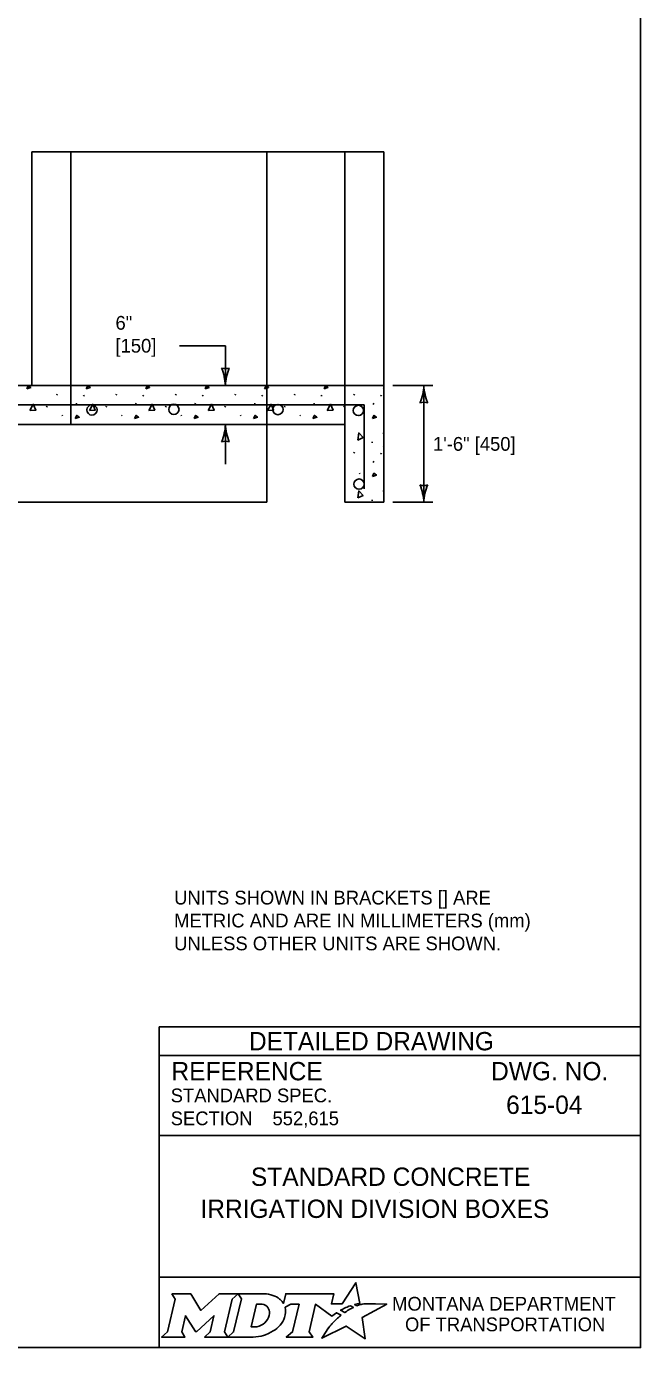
# Model space of a CAD drawing. Extents: x 49991.4 to 50021, y 49987.6 to 50011.4.
# Drawn here: x 50014.07 to 50016.75, y 49987.8 to 49993.57 of the extents above; entities that cross this region are included whole.
import ezdxf

# ---------------------------------------------------------------- set-up
doc = ezdxf.new("R2010")
doc.units = 0
for name, color, linetype in [('Default', 7, 'Continuous'), ('Level 1', 7, 'Continuous'), ('Level 2', 7, 'Continuous'), ('Level 3', 7, 'Continuous'), ('Level 4', 7, 'Continuous'), ('Level 5', 7, 'Continuous')]:
    doc.layers.add(name, color=color, linetype=linetype)

msp = doc.modelspace()

# ---------------------------------------------------------------- linework, layer by layer
at = {"layer": 'Default'}
for points in [[(50015.5126, 49987.9811), (50015.5023, 49987.9867), (50015.5139, 49987.9895), (50015.5255, 49987.9915), (50015.5081, 49988.0816), (50015.4486, 49987.9903), (50015.4013, 49987.9896), (50015.4116, 49988.0337), (50015.2024, 49988.0338), (50015.1923, 49987.9913), (50015.1865, 49987.9996)], [(50014.7056, 49988.0338), (50014.7197, 49988.0104), (50014.6862, 49987.8671), (50014.6605, 49987.8446), (50014.7621, 49987.8446), (50014.7486, 49987.8674), (50014.7648, 49987.9375), (50014.8085, 49987.8685), (50014.8138, 49987.8685), (50014.8889, 49987.938), (50014.8725, 49987.8669), (50014.8478, 49987.8449), (50014.9494, 49987.8449), (50014.9356, 49987.8682), (50014.9688, 49988.0106)], [(50014.9688, 49988.0106), (50014.9941, 49988.0338), (50014.9117, 49988.0338), (50014.8321, 49987.9608), (50014.7876, 49988.0335), (50014.7056, 49988.0338)], [(50015.1077, 49988.0338), (50014.9941, 49988.0338), (50015.0088, 49988.0109), (50014.9749, 49987.8671), (50014.9494, 49987.8449), (50015.06, 49987.8449)], [(50015.1317, 49987.9471), (50015.1305, 49987.939), (50015.1273, 49987.9297), (50015.1231, 49987.9215), (50015.1175, 49987.914), (50015.111, 49987.9071), (50015.1031, 49987.9008), (50015.0948, 49987.8961), (50015.0857, 49987.8922), (50015.0766, 49987.8899), (50015.0674, 49987.889), (50015.0515, 49987.889), (50015.0751, 49987.989), (50015.0911, 49987.989), (50015.0987, 49987.9884), (50015.1063, 49987.9865), (50015.1129, 49987.9835), (50015.119, 49987.9793), (50015.1238, 49987.9743), (50015.1275, 49987.9683), (50015.1302, 49987.9621), (50015.1318, 49987.9547), (50015.1318, 49987.9517), (50015.1317, 49987.9471)], [(50015.1991, 49987.9747), (50015.2237, 49987.9878), (50015.2606, 49987.9878), (50015.232, 49987.8673), (50015.2045, 49987.8446), (50015.3207, 49987.8446), (50015.3037, 49987.8675), (50015.3319, 49987.9877), (50015.4032, 49987.936), (50015.4243, 49987.9511), (50015.444, 49987.9402)], [(50015.3882, 49987.8843), (50015.3729, 49987.8599), (50015.3682, 49987.8524), (50015.3624, 49987.8438), (50015.3601, 49987.8395), (50015.4654, 49987.8926), (50015.5493, 49987.8375), (50015.5362, 49987.9302), (50015.6431, 49987.9886), (50015.5938, 49987.9894), (50015.5637, 49987.9898), (50015.5429, 49987.9901), (50015.5361, 49987.9886), (50015.5312, 49987.9874), (50015.5228, 49987.9851), (50015.5126, 49987.9811)], [(50015.4622, 49987.9535), (50015.4598, 49987.9518), (50015.4415, 49987.9614), (50015.4518, 49987.9671), (50015.4559, 49987.9693), (50015.4645, 49987.9733), (50015.4702, 49987.9759), (50015.4781, 49987.9789), (50015.4854, 49987.9816), (50015.4972, 49987.9742), (50015.4932, 49987.9721), (50015.4886, 49987.9696), (50015.4844, 49987.9674), (50015.4794, 49987.9645), (50015.4775, 49987.9634), (50015.4748, 49987.9618), (50015.4723, 49987.9604), (50015.47, 49987.9588), (50015.4674, 49987.957), (50015.4647, 49987.9552), (50015.4622, 49987.9535)], [(50015.1057, 49987.8522), (50015.1141, 49987.8548), (50015.1271, 49987.8602), (50015.1475, 49987.8712)], [(50015.4021, 49987.9004), (50015.4021, 49987.9004)]]:
    msp.add_lwpolyline(points, dxfattribs=at)
for centre, radius, start, end in [((50015.0868, 49987.9727), 0.1183, 300.91025, 339.13831), ((50015.1308, 49987.9554), 0.0709, 339.53292, 15.85821)]:
    msp.add_arc(centre, radius, start, end, dxfattribs=at)
for centre, major_axis, ratio, start_param, end_param in [((50015.1056, 49987.9864), (0.0834, -0.0037), 0.568097, 0.61298, 1.570796), ((50015.1612, 49987.9937), (0.0361, -0.0295), 0.469099, 1.225588, 1.570796), ((50015.4329, 49987.9305), (-0.0112, -0.0097), 0.021651, 3.157348, 6.283185), ((50015.3952, 49987.8923), (-0.00694, -0.00806), 0.008222, 0, 3.137361), ((50015.4119, 49987.9106), (-0.0098, -0.0102), 0.016458, 3.141593, 6.279097), ((50015.0603, 49987.9932), (0, 0.1484), 0.987302, 3.139398, 3.456847)]:
    msp.add_ellipse(centre, major_axis=major_axis, ratio=ratio, start_param=start_param, end_param=end_param, dxfattribs=at)
at = {"layer": 'Level 1'}
for p, q in [((50014.0942, 49991.9984), (50014.0942, 49993.0183)), ((50014.0942, 49993.0183), (50015.3051, 49993.0183)), ((50015.3051, 49993.0183), (50015.6295, 49993.0183)), ((50015.6295, 49991.9984), (50015.6295, 49993.0183)), ((50011.8896, 49991.9984), (50015.6295, 49991.9984)), ((50014.203, 49991.9558), (50014.2052, 49991.9607)), ((50014.4623, 49991.9558), (50014.4645, 49991.9607)), ((50014.7217, 49991.9558), (50014.7238, 49991.9607)), ((50014.981, 49991.9558), (50014.9831, 49991.9607)), ((50015.2403, 49991.9558), (50015.2424, 49991.9607)), ((50015.4996, 49991.9558), (50015.5017, 49991.9607)), ((50015.6295, 49991.4884), (50015.6295, 49991.9984)), ((50011.9746, 49991.9134), (50015.5445, 49991.9134)), ((50014.1592, 49991.9032), (50014.1613, 49991.9081)), ((50014.2875, 49991.9157), (50014.2896, 49991.9205)), ((50014.3194, 49991.9558), (50014.3216, 49991.9526)), ((50014.3216, 49991.9546), (50014.3238, 49991.9513)), ((50014.4185, 49991.9032), (50014.4207, 49991.9081)), ((50014.5468, 49991.9157), (50014.549, 49991.9205)), ((50014.5787, 49991.9558), (50014.5809, 49991.9526)), ((50014.5809, 49991.9546), (50014.5831, 49991.9513)), ((50014.6778, 49991.9032), (50014.68, 49991.9081)), ((50014.8061, 49991.9157), (50014.8083, 49991.9205)), ((50014.838, 49991.9558), (50014.8402, 49991.9526)), ((50014.8402, 49991.9546), (50014.8424, 49991.9513)), ((50014.9371, 49991.9032), (50014.9393, 49991.9081)), ((50015.0654, 49991.9157), (50015.0676, 49991.9205)), ((50015.0974, 49991.9558), (50015.0995, 49991.9526)), ((50015.0995, 49991.9546), (50015.1017, 49991.9513)), ((50015.1964, 49991.9032), (50015.1986, 49991.9081)), ((50015.3247, 49991.9157), (50015.3269, 49991.9205)), ((50015.3567, 49991.9558), (50015.3588, 49991.9526)), ((50015.3588, 49991.9546), (50015.361, 49991.9513)), ((50015.4557, 49991.9032), (50015.4579, 49991.9081)), ((50015.5445, 49991.5473), (50015.5445, 49991.9134)), ((50015.584, 49991.9157), (50015.5862, 49991.9205)), ((50015.616, 49991.9558), (50015.6181, 49991.9526)), ((50015.6181, 49991.9546), (50015.6203, 49991.9513)), ((50014.2269, 49991.8686), (50014.229, 49991.8653)), ((50014.4862, 49991.8686), (50014.4883, 49991.8653)), ((50014.7455, 49991.8686), (50014.7476, 49991.8653)), ((50015.0048, 49991.8686), (50015.0069, 49991.8653)), ((50015.2641, 49991.8686), (50015.2663, 49991.8653)), ((50015.5234, 49991.8686), (50015.5256, 49991.8653)), ((50012.0596, 49991.8284), (50015.4595, 49991.8284)), ((50015.1195, 49991.4884), (50015.1195, 49991.8284)), ((50015.4595, 49991.4884), (50015.4595, 49991.8284)), ((50015.6273, 49991.7879), (50015.6295, 49991.7928)), ((50015.579, 49991.7521), (50015.5796, 49991.7473)), ((50015.4996, 49991.7029), (50015.5017, 49991.7078)), ((50015.616, 49991.7029), (50015.6181, 49991.6997)), ((50015.6181, 49991.7017), (50015.6203, 49991.6984)), ((50015.5234, 49991.6157), (50015.5256, 49991.6125)), ((50015.584, 49991.6628), (50015.5862, 49991.6677)), ((50015.579, 49991.4993), (50015.5796, 49991.4944)), ((50015.6273, 49991.535), (50015.6295, 49991.5399)), ((50012.3996, 49991.4884), (50015.1195, 49991.4884)), ((50015.4595, 49991.4884), (50015.6295, 49991.4884))]:
    msp.add_line(p, q, dxfattribs=at)
msp.add_lwpolyline([(49999.3835, 49998.9992), (50016.7501, 49998.9992), (50016.7501, 49987.7988), (49999.3835, 49987.7988)], close=True, dxfattribs=at)
for points in [[(50014.0726, 49991.9839), (50014.0791, 49991.9975), (50014.0899, 49991.9894), (50014.0726, 49991.9839)], [(50014.3319, 49991.9839), (50014.3384, 49991.9975), (50014.3492, 49991.9894), (50014.3319, 49991.9839)], [(50014.5912, 49991.9839), (50014.5977, 49991.9975), (50014.6085, 49991.9894), (50014.5912, 49991.9839)], [(50014.8505, 49991.9839), (50014.857, 49991.9975), (50014.8678, 49991.9894), (50014.8505, 49991.9839)], [(50015.1098, 49991.9839), (50015.1163, 49991.9975), (50015.1271, 49991.9894), (50015.1098, 49991.9839)], [(50015.3691, 49991.9839), (50015.3756, 49991.9975), (50015.3864, 49991.9894), (50015.3691, 49991.9839)], [(50015.6284, 49991.9839), (50015.6295, 49991.9862)], [(50015.6295, 49991.9842), (50015.6284, 49991.9839)], [(50014.0861, 49991.8886), (50014.1007, 49991.9162), (50014.1121, 49991.8908), (50014.0866, 49991.8886)], [(50014.3454, 49991.8886), (50014.36, 49991.9162), (50014.3714, 49991.8908), (50014.346, 49991.8886)], [(50014.6047, 49991.8886), (50014.6193, 49991.9162), (50014.6307, 49991.8908), (50014.6053, 49991.8886)], [(50014.864, 49991.8886), (50014.8787, 49991.9162), (50014.89, 49991.8908), (50014.8646, 49991.8886)], [(50015.1233, 49991.8886), (50015.138, 49991.9162), (50015.1493, 49991.8908), (50015.1239, 49991.8886)], [(50015.3827, 49991.8886), (50015.3973, 49991.9162), (50015.4086, 49991.8908), (50015.3832, 49991.8886)], [(50014.2837, 49991.8545), (50014.2902, 49991.868), (50014.301, 49991.8599), (50014.2837, 49991.8545)], [(50014.543, 49991.8545), (50014.5495, 49991.868), (50014.5603, 49991.8599), (50014.543, 49991.8545)], [(50014.8023, 49991.8545), (50014.8088, 49991.868), (50014.8196, 49991.8599), (50014.8023, 49991.8545)], [(50015.0616, 49991.8545), (50015.0681, 49991.868), (50015.0789, 49991.8599), (50015.0616, 49991.8545)], [(50015.3209, 49991.8545), (50015.3274, 49991.868), (50015.3383, 49991.8599), (50015.3209, 49991.8545)], [(50015.5802, 49991.8545), (50015.5867, 49991.868), (50015.5976, 49991.8599), (50015.5802, 49991.8545)], [(50014.1491, 49991.8284), (50014.1495, 49991.8293), (50014.1507, 49991.8284)], [(50014.4085, 49991.8284), (50014.4089, 49991.8293), (50014.4101, 49991.8284)], [(50014.6678, 49991.8284), (50014.6682, 49991.8293), (50014.6694, 49991.8284)], [(50014.9271, 49991.8284), (50014.9275, 49991.8293), (50014.9287, 49991.8284)], [(50015.1864, 49991.8284), (50015.1868, 49991.8293), (50015.188, 49991.8284)], [(50015.4457, 49991.8284), (50015.4461, 49991.8293), (50015.4473, 49991.8284)], [(50015.5162, 49991.7601), (50015.5205, 49991.7911), (50015.5399, 49991.771), (50015.5167, 49991.7603)], [(50015.6284, 49991.7311), (50015.6295, 49991.7334)], [(50015.6295, 49991.7314), (50015.6284, 49991.7311)], [(50015.5802, 49991.6016), (50015.5867, 49991.6152), (50015.5976, 49991.607), (50015.5802, 49991.6016)], [(50015.5162, 49991.5073), (50015.5205, 49991.5382), (50015.5399, 49991.5182), (50015.5167, 49991.5074)]]:
    msp.add_lwpolyline(points, dxfattribs=at)
for centre in [(50014.3569, 49991.8914), (50014.7144, 49991.8942), (50015.1682, 49991.8933), (50015.519, 49991.8893), (50015.5219, 49991.568)]:
    msp.add_circle(centre, 0.0224, dxfattribs=at)
at = {"layer": 'Level 3'}
for p, q in [((50014.9389, 49992.1718), (50014.7389, 49992.1718)), ((50014.9389, 49991.9984), (50014.9389, 49992.1718)), ((50015.6695, 49991.9984), (50015.8446, 49991.9984)), ((50015.8046, 49991.4884), (50015.8046, 49991.9984)), ((50014.9389, 49991.8284), (50014.9389, 49991.655)), ((50015.6695, 49991.4884), (50015.8446, 49991.4884))]:
    msp.add_line(p, q, dxfattribs=at)
for centre, radius, start, end in [((50014.9389, 49992.1266), 0.0548, 252.13882, 287.86118), ((50014.7062, 49991.9869), 0.233, 2.82731, 22.07716), ((50015.161, 49991.9892), 0.2223, 157.45601, 177.63952), ((50015.5825, 49992.0075), 0.2223, 337.45601, 357.63952), ((50016.0373, 49992.0099), 0.233, 182.82731, 202.07716), ((50015.8046, 49991.8702), 0.0548, 72.13882, 107.86118), ((50014.7168, 49991.8375), 0.2223, 337.45601, 357.63952), ((50015.1716, 49991.8399), 0.233, 182.82731, 202.07716), ((50014.9389, 49991.7002), 0.0548, 72.13882, 107.86118), ((50015.8046, 49991.6166), 0.0548, 252.13882, 287.86118), ((50015.5719, 49991.4769), 0.233, 2.82731, 22.07716), ((50016.0267, 49991.4792), 0.2223, 157.45601, 177.63952)]:
    msp.add_arc(centre, radius, start, end, dxfattribs=at)
at = {"layer": 'Level 4'}
for p, q in [((50014.2642, 49991.8284), (50014.2642, 49993.0183)), ((50015.1195, 49991.8284), (50015.1195, 49993.0183)), ((50015.4595, 49991.8284), (50015.4595, 49993.0183))]:
    msp.add_line(p, q, dxfattribs=at)
at = {"layer": 'Level 5'}
for p, q in [((50016.7501, 49989.1988), (50014.6501, 49989.1988)), ((50014.6501, 49989.1988), (50014.6501, 49987.7988)), ((50016.7501, 49989.0738), (50014.6501, 49989.0738)), ((50016.3862, 49988.8587), (50016.3862, 49988.8587)), ((50015.1444, 49988.7993), (50015.1444, 49988.7993)), ((50016.7501, 49988.7238), (50014.6501, 49988.7238)), ((50015.7001, 49988.4747), (50015.7001, 49988.4747)), ((50016.7501, 49988.1057), (50014.6501, 49988.1057))]:
    msp.add_line(p, q, dxfattribs=at)

# ---------------------------------------------------------------- texts
at = {"layer": 'Default'}
for s, p in [('MONTANA DEPARTMENT', (50015.6663, 49987.96)), ('OF TRANSPORTATION', (50015.7225, 49987.87))]:
    msp.add_text(s, height=0.06, dxfattribs=at).set_placement(p)
at = {"layer": 'Level 2'}
for s, height, p in [('6"', 0.06, (50014.4594, 49992.2418)), ('[150]', 0.06, (50014.4594, 49992.1418)), ('1\'-6" [450]', 0.06, (50015.8446, 49991.7134)), ('UNITS SHOWN IN BRACKETS [] ARE ', 0.06, (50014.7152, 49989.7328)), ('METRIC AND ARE IN MILLIMETERS (mm) ', 0.06, (50014.7152, 49989.6328)), ('UNLESS OTHER UNITS ARE SHOWN.', 0.06, (50014.7152, 49989.5328)), ('615-04', 0.08, (50016.1636, 49988.8187)), ('552,615', 0.06, (50015.1444, 49988.7693)), ('STANDARD CONCRETE', 0.08, (50015.0503, 49988.5047)), ('IRRIGATION DIVISION BOXES', 0.08, (50014.8302, 49988.3647))]:
    msp.add_text(s, height=height, dxfattribs=at).set_placement(p)
at = {"layer": 'Level 5'}
for s, height, p in [('DETAILED DRAWING', 0.0799, (50015.0418, 49989.0963)), ('REFERENCE', 0.08, (50014.7037, 49988.9654)), ('DWG. NO.', 0.08, (50016.0979, 49988.9654)), ('STANDARD SPEC.', 0.06, (50014.7004, 49988.8694)), ('SECTION', 0.06, (50014.7004, 49988.7694))]:
    msp.add_text(s, height=height, dxfattribs=at).set_placement(p)

doc.saveas('drawing.dxf')
